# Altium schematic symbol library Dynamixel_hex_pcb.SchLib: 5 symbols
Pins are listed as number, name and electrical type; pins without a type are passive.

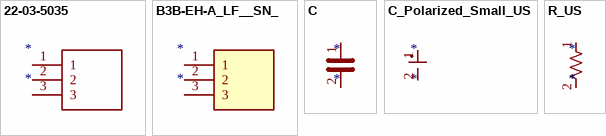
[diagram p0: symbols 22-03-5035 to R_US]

## 22-03-5035
designator *
pins: 1, 2, 3

## B3B-EH-A_LF__SN_
designator *
pins: 1, 2, 3

## C
designator *
pins: 1, 2

## C_Polarized_Small_US
designator *
pins: 1, 2

## R_US
designator *
pins: 1, 2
